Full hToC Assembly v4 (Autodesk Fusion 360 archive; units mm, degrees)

design "Full hToC Assembly" references "1 Slot Membrane", "hToc Bottom Component", "v10_component1"
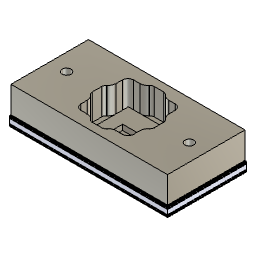
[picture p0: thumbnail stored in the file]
component_insert "Component Insert1"
component_insert "Component Insert2"
component_insert "Component Insert4"

design "v10_component1"
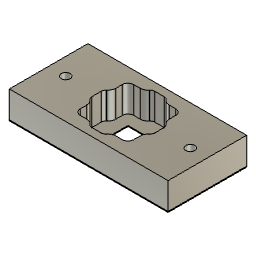
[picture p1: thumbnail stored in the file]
sketch "Sketch1" plane through (0, 0, 0) normal (0, 0, 1) x axis (1, 0, 0)
  line L1 (17.82, 5.59) -> (0, 5.59)
  line L2 (17.82, 8.82) -> (17.82, 0)
  line L3 (9.8201, 1.0463) -> (9.8489, 1.0851)
  line L4 (6.544, 1.41) -> (7.2771, 1.41)
  line L5 (10.5429, 7.41) -> (11.276, 7.41)
  line L6 (12.2349, 3.4711) -> (12.2737, 3.4999)
  line L7 (1.92, 4.41) -> (15.9, 4.41)
  line L8 (0, 3.621) -> (17.82, 3.621)
  line L9 (12.2737, 5.3201) -> (12.2349, 5.3489)
  line L10 (10.09, 0) -> (10.09, 8.82)
  line L11 (11.276, 1.41) -> (10.5429, 1.41)
  line L12 (9.699, 8.82) -> (9.699, 0)
  line L13 (5.5851, 5.3489) -> (5.5463, 5.3201)
  line L14 (12.437, 4.9474) -> (12.437, 3.8726)
  line L15 (17.82, 4.41) -> (15.9, 4.41)
  line L16 (15.9, 8.82) -> (15.9, 4.41)
  line L17 (5.5463, 3.4999) -> (5.5851, 3.4711)
  line L18 (17.82, 0) -> (0, 0)
  line L19 (17.82, 5.199) -> (0, 5.199)
  line L20 (17.82, 3.23) -> (0, 3.23)
  line L21 (0, 0) -> (0, 8.82)
  line L22 (11.91, 2.7771) -> (11.91, 2.044)
  line L23 (1.92, 4.41) -> (0, 4.41)
  line L24 (8.3726, 0.883) -> (9.4474, 0.883)
  line L25 (5.91, 2.7771) -> (5.91, 2.044)
  line L26 (1.92, 0) -> (1.92, 4.41)
  line L27 (15.9, 0) -> (15.9, 4.41)
  line L28 (9.4474, 7.937) -> (8.3726, 7.937)
  line L29 (5.383, 3.8726) -> (5.383, 4.9474)
  line L30 (9.8489, 7.7349) -> (9.8201, 7.7737)
  line L31 (5.91, 6.0429) -> (5.91, 6.776)
  line L32 (7.2771, 7.41) -> (6.544, 7.41)
  line L33 (7.9999, 7.7737) -> (7.9711, 7.7349)
  line L34 (8.121, 0) -> (8.121, 8.82)
  line L35 (1.92, 8.82) -> (1.92, 4.41)
  line L36 (7.9999, 1.0463) -> (7.9711, 1.0851)
  line L37 (11.91, 6.0429) -> (11.91, 6.776)
  line L38 (0, 8.82) -> (17.82, 8.82)
  line L39 (7.73, 8.82) -> (7.73, 0)
  arc A1 centre (12.81, 6.0429) radius 0.9 clockwise from (12.2737, 5.3201) to (11.91, 6.0429)
  arc A2 centre (11.937, 3.8726) radius 0.5 clockwise from (12.437, 3.8726) to (12.2349, 3.4711)
  arc A3 centre (9.4474, 1.383) radius 0.5 clockwise from (9.8489, 1.0851) to (9.4474, 0.883)
  arc A4 centre (11.276, 6.776) radius 0.634 clockwise from (11.276, 7.41) to (11.91, 6.776)
  arc A5 centre (9.4474, 7.437) radius 0.5 clockwise from (9.4474, 7.937) to (9.8489, 7.7349)
  arc A6 centre (11.937, 4.9474) radius 0.5 clockwise from (12.2349, 5.3489) to (12.437, 4.9474)
  arc A7 centre (10.5429, 8.31) radius 0.9 clockwise from (10.5429, 7.41) to (9.8201, 7.7737)
  circle C1 centre (15.9, 4.41) radius 0.5
  circle C2 centre (1.92, 4.41) radius 0.5
  arc A8 centre (8.3726, 7.437) radius 0.5 clockwise from (7.9711, 7.7349) to (8.3726, 7.937)
  arc A9 centre (10.5429, 0.51) radius 0.9 clockwise from (9.8201, 1.0463) to (10.5429, 1.41)
  arc A10 centre (5.01, 6.0429) radius 0.9 clockwise from (5.91, 6.0429) to (5.5463, 5.3201)
  arc A11 centre (5.883, 3.8726) radius 0.5 clockwise from (5.5851, 3.4711) to (5.383, 3.8726)
  arc A12 centre (8.3726, 1.383) radius 0.5 clockwise from (8.3726, 0.883) to (7.9711, 1.0851)
  arc A13 centre (6.544, 2.044) radius 0.634 clockwise from (6.544, 1.41) to (5.91, 2.044)
  arc A14 centre (5.883, 4.9474) radius 0.5 clockwise from (5.383, 4.9474) to (5.5851, 5.3489)
  arc A15 centre (7.2771, 8.31) radius 0.9 clockwise from (7.9999, 7.7737) to (7.2771, 7.41)
  arc A16 centre (5.01, 2.7771) radius 0.9 clockwise from (5.5463, 3.4999) to (5.91, 2.7771)
  arc A17 centre (12.81, 2.7771) radius 0.9 clockwise from (11.91, 2.7771) to (12.2737, 3.4999)
  arc A18 centre (11.276, 2.044) radius 0.634 clockwise from (11.91, 2.044) to (11.276, 1.41)
  arc A19 centre (7.2771, 0.51) radius 0.9 clockwise from (7.2771, 1.41) to (7.9999, 1.0463)
  arc A20 centre (6.544, 6.776) radius 0.634 clockwise from (5.91, 6.776) to (6.544, 7.41)
  point P28 (0, 0)
  point P80 (0, 0)
  point P29 (1.92, 4.41)
  point P34 (1.92, 4.41)
  point P35 (1.92, 8.82)
  point P31 (1.92, 4.41)
  point P30 (1.92, 0)
  point P15 (15.9, 4.41)
  point P39 (15.9, 4.41)
  point P38 (15.9, 8.82)
  point P36 (15.9, 4.41)
  point P37 (15.9, 0)
  point P5 (15.9, 4.41)
  point P6 (17.82, 4.41)
  point P27 (15.9, 4.41)
  point P82 (1.92, 4.41)
  point P33 (0, 4.41)
  point P32 (1.92, 4.41)
  point P98 (0, 5.199)
  point P95 (17.82, 5.199)
  point P89 (17.82, 3.621)
  point P90 (0, 3.621)
  point P41 (0, 3.23)
  point P97 (0, 5.59)
  point P93 (17.82, 5.59)
  point P96 (8.121, 8.82)
  point P92 (8.121, 0)
  point P81 (9.699, 0)
  point P83 (9.699, 8.82)
  point P88 (10.09, 8.82)
  point P84 (10.09, 0)
  point P91 (7.73, 0)
  point P94 (7.73, 8.82)
  point P65 (11.276, 1.41)
  point P20 (11.91, 6.776)
  point P57 (6.544, 7.41)
  point P22 (5.91, 2.044)
  horizontal L18
  vertical L2
  horizontal L38
  vertical L21
  coincident P28 P80
  coincident P29 P34
  coincident P35 L38
  perpendicular L35 L38
  coincident P29 P31
  coincident P30 L18
  perpendicular L18 L26
  coincident P15 P39
  coincident P38 L38
  perpendicular L16 L38
  coincident P15 P36
  coincident P37 L18
  perpendicular L18 L27
  coincident P5 P15
  midpoint P6 L2
  coincident P15 P27
  coincident P29 P82
  perpendicular L7 L26
  midpoint P33 L21
  coincident P29 P32
  perpendicular L23 L26
  coincident P98 L21
  coincident P95 L2
  perpendicular L2 L19
  coincident P89 L2
  coincident P90 L21
  perpendicular L8 L21
  coincident P41 L21
  perpendicular L20 L21
  perpendicular L4 L21
  coincident P97 L21
  coincident P93 L2
  perpendicular L1 L2
  perpendicular L5 L21
  coincident P96 L38
  coincident P92 L18
  perpendicular L18 L34
  coincident P81 L18
  coincident P83 L38
  perpendicular L12 L38
  coincident P88 L38
  coincident P84 L18
  perpendicular L10 L18
  perpendicular L22 L38
  coincident P91 L18
  coincident P94 L38
  perpendicular L38 L39
  perpendicular L18 L31
  perpendicular L18 L29
  perpendicular L14 L38
  perpendicular L2 L28
  perpendicular L21 L24
  tangent L31 A20
  tangent L5 A20
  tangent L5 A4
  tangent A4 L22
  tangent L4 A13
  tangent A13 L31
  tangent L4 A18
  tangent L22 A18
  coincident P65 L4
  tangent L4 A19
  tangent A19 L36
  tangent A12 L36
  tangent L24 A12
  tangent A3 L24
  tangent L3 A3
  tangent L3 A9
  tangent L11 A9
  coincident P20 L22
  tangent L22 A17
  tangent L6 A17
  tangent L6 A2
  tangent A2 L14
  tangent A6 L14
  tangent L9 A6
  tangent A1 L9
  tangent A1 L37
  coincident P57 L5
  tangent A7 L30
  tangent L5 A7
  tangent A5 L28
  tangent A5 L30
  tangent A15 L32
  tangent A15 L33
  tangent A8 L33
  tangent A8 L28
  coincident P22 L31
  tangent L13 A10
  tangent A10 L31
  tangent A14 L29
  tangent L13 A14
  tangent L17 A11
  tangent A11 L29
  tangent L17 A16
  tangent L25 A16
  dimension "d1" distance L2 L21 = 17.82
  dimension "d2" distance L18 L38 = 8.82
  dimension "d3" diameter C2 = 1
  dimension "d4" diameter C1 = 1
  dimension "d5" distance L21 L26 = 1.92
  dimension "d6" distance L2 L27 = 1.92
  dimension "d7" distance L12 L34 = 1.578
  dimension "d8" distance L2 L12 = 8.121
  dimension "d9" distance L10 L39 = 2.36
  dimension "d10" distance L2 L10 = 7.73
  dimension "d11" distance L22 L31 = 6
  dimension "d12" distance L2 L22 = 5.91
  dimension "d13" distance L14 L29 = 7.054
  dimension "d14" distance L2 L14 = 5.383
  dimension "d15" distance L8 L19 = 1.578
  dimension "d16" distance L19 L38 = 3.621
  dimension "d17" distance L1 L20 = 2.36
  dimension "d18" distance L1 L38 = 3.23
  dimension "d19" distance L4 L5 = 6
  dimension "d20" distance L5 L38 = 1.41
  dimension "d21" distance L24 L28 = 7.054
  dimension "d22" distance L28 L38 = 0.883
  dimension "d23" radius A20 = 0.634
  dimension "d24" radius A4 = 0.634
  dimension "d25" radius A13 = 0.634
  dimension "d26" radius A18 = 0.634
  dimension "d27" radius A19 = 0.9
  dimension "d28" radius A12 = 0.5
  dimension "d29" radius A3 = 0.5
  dimension "d30" radius A9 = 0.9
  dimension "d31" radius A17 = 0.9
  dimension "d32" radius A2 = 0.5
  dimension "d33" radius A6 = 0.5
  dimension "d34" radius A1 = 0.9
  dimension "d35" radius A7 = 0.9
  dimension "d36" radius A5 = 0.5
  dimension "d37" radius A15 = 0.9
  dimension "d38" radius A8 = 0.5
  dimension "d39" radius A10 = 0.9
  dimension "d40" radius A14 = 0.5
  dimension "d41" radius A11 = 0.5
  dimension "d42" radius A16 = 0.9
extrude "Extrude1" new body sketch "Sketch1" along normal blind 3 bodies "L1 - ACRYLIC"
sketch "Sketch2" plane through (0, 0, 3) normal (0, 0, 1) x axis (-1, 0, 0)
  line L1 (-7.2771, -7.41) -> (-6.544, -7.41)
  line L2 (-7.9711, -7.7349) -> (-7.9999, -7.7737)
  line L3 (-9.4474, -7.937) -> (-8.3726, -7.937)
  line L4 (-9.8201, -7.7737) -> (-9.8489, -7.7349)
  line L5 (-11.276, -7.41) -> (-10.5429, -7.41)
  line L6 (-11.91, -6.0429) -> (-11.91, -6.776)
  line L7 (-12.2349, -5.3489) -> (-12.2737, -5.3201)
  line L8 (-12.437, -3.8726) -> (-12.437, -4.9474)
  line L9 (-12.2737, -3.4999) -> (-12.2349, -3.4711)
  line L10 (-11.91, -2.044) -> (-11.91, -2.7771)
  line L11 (-10.5429, -1.41) -> (-11.276, -1.41)
  line L12 (-9.8489, -1.0851) -> (-9.8201, -1.0463)
  line L13 (-8.3726, -0.883) -> (-9.4474, -0.883)
  line L14 (-7.9999, -1.0463) -> (-7.9711, -1.0851)
  line L15 (-6.544, -1.41) -> (-7.2771, -1.41)
  line L16 (-5.91, -2.7771) -> (-5.91, -2.044)
  line L17 (-5.5851, -3.4711) -> (-5.5463, -3.4999)
  line L18 (-5.383, -4.9474) -> (-5.383, -3.8726)
  line L19 (-5.5463, -5.3201) -> (-5.5851, -5.3489)
  line L20 (-5.91, -6.776) -> (-5.91, -6.0429)
  line L21 (0, -8.82) -> (-17.82, -8.82)
  line L22 (0, 0) -> (0, -8.82)
  line L23 (-17.82, 0) -> (0, 0)
  line L24 (-17.82, -8.82) -> (-17.82, 0)
  circle C1 centre (-1.92, -4.41) radius 0.5
  arc A1 centre (-7.2771, -8.31) radius 0.9 clockwise from (-7.9999, -7.7737) to (-7.2771, -7.41)
  arc A2 centre (-8.3726, -7.437) radius 0.5 clockwise from (-7.9711, -7.7349) to (-8.3726, -7.937)
  arc A3 centre (-9.4474, -7.437) radius 0.5 clockwise from (-9.4474, -7.937) to (-9.8489, -7.7349)
  arc A4 centre (-10.5429, -8.31) radius 0.9 clockwise from (-10.5429, -7.41) to (-9.8201, -7.7737)
  arc A5 centre (-11.276, -6.776) radius 0.634 clockwise from (-11.276, -7.41) to (-11.91, -6.776)
  arc A6 centre (-12.81, -6.0429) radius 0.9 clockwise from (-12.2737, -5.3201) to (-11.91, -6.0429)
  arc A7 centre (-11.937, -4.9474) radius 0.5 clockwise from (-12.2349, -5.3489) to (-12.437, -4.9474)
  arc A8 centre (-11.937, -3.8726) radius 0.5 clockwise from (-12.437, -3.8726) to (-12.2349, -3.4711)
  arc A9 centre (-12.81, -2.7771) radius 0.9 clockwise from (-11.91, -2.7771) to (-12.2737, -3.4999)
  arc A10 centre (-11.276, -2.044) radius 0.634 clockwise from (-11.91, -2.044) to (-11.276, -1.41)
  arc A11 centre (-10.5429, -0.51) radius 0.9 clockwise from (-9.8201, -1.0463) to (-10.5429, -1.41)
  arc A12 centre (-9.4474, -1.383) radius 0.5 clockwise from (-9.8489, -1.0851) to (-9.4474, -0.883)
  arc A13 centre (-8.3726, -1.383) radius 0.5 clockwise from (-8.3726, -0.883) to (-7.9711, -1.0851)
  arc A14 centre (-7.2771, -0.51) radius 0.9 clockwise from (-7.2771, -1.41) to (-7.9999, -1.0463)
  arc A15 centre (-6.544, -2.044) radius 0.634 clockwise from (-6.544, -1.41) to (-5.91, -2.044)
  arc A16 centre (-5.01, -2.7771) radius 0.9 clockwise from (-5.5463, -3.4999) to (-5.91, -2.7771)
  arc A17 centre (-5.883, -3.8726) radius 0.5 clockwise from (-5.5851, -3.4711) to (-5.383, -3.8726)
  arc A18 centre (-5.883, -4.9474) radius 0.5 clockwise from (-5.383, -4.9474) to (-5.5851, -5.3489)
  arc A19 centre (-5.01, -6.0429) radius 0.9 clockwise from (-5.91, -6.0429) to (-5.5463, -5.3201)
  arc A20 centre (-6.544, -6.776) radius 0.634 clockwise from (-5.91, -6.776) to (-6.544, -7.41)
  circle C2 centre (-15.9, -4.41) radius 0.5
sketch "Sketch3" plane through (0, 0, 0) normal (0, 0, -1) x axis (1, 0, 0)
  line L1 (6.544, -7.41) -> (7.2771, -7.41)
  line L2 (5.91, -6.0429) -> (5.91, -6.776)
  line L3 (5.5851, -5.3489) -> (5.5463, -5.3201)
  line L4 (5.383, -3.8726) -> (5.383, -4.9474)
  line L5 (5.5463, -3.4999) -> (5.5851, -3.4711)
  line L6 (5.91, -2.044) -> (5.91, -2.7771)
  line L7 (7.2771, -1.41) -> (6.544, -1.41)
  line L8 (7.9711, -1.0851) -> (7.9999, -1.0463)
  line L9 (9.4474, -0.883) -> (8.3726, -0.883)
  line L10 (9.8201, -1.0463) -> (9.8489, -1.0851)
  line L11 (11.276, -1.41) -> (10.5429, -1.41)
  line L12 (11.91, -2.7771) -> (11.91, -2.044)
  line L13 (12.2349, -3.4711) -> (12.2737, -3.4999)
  line L14 (12.437, -4.9474) -> (12.437, -3.8726)
  line L15 (12.2737, -5.3201) -> (12.2349, -5.3489)
  line L16 (11.91, -6.776) -> (11.91, -6.0429)
  line L17 (10.5429, -7.41) -> (11.276, -7.41)
  line L18 (9.8489, -7.7349) -> (9.8201, -7.7737)
  line L19 (8.3726, -7.937) -> (9.4474, -7.937)
  line L20 (7.9999, -7.7737) -> (7.9711, -7.7349)
  line L21 (17.82, -8.82) -> (0, -8.82)
  line L22 (17.82, 0) -> (17.82, -8.82)
  line L23 (0, 0) -> (17.82, 0)
  line L24 (0, -8.82) -> (0, 0)
  line L25 (17.82, -8.82) -> (17.82, 0)
  line L26 (17.82, 0) -> (0, 0)
  line L27 (7.21, -2.71) -> (10.61, -2.71)
  line L28 (10.61, -2.71) -> (10.61, -6.11)
  line L29 (10.61, -6.11) -> (7.21, -6.11)
  line L30 (0, 0) -> (0, -8.82)
  line L31 (7.21, -6.11) -> (7.21, -2.71)
  line L32 (15.9, -4.41) -> (1.92, -4.41)
  line L33 (0, -4.41) -> (1.92, -4.41)
  line L34 (17.82, -4.41) -> (15.9, -4.41)
  line L35 (0, -8.82) -> (17.82, -8.82)
  circle C1 centre (1.92, -4.41) radius 0.5
  arc A1 centre (6.544, -6.776) radius 0.634 clockwise from (6.544, -7.41) to (5.91, -6.776)
  arc A2 centre (5.01, -6.0429) radius 0.9 clockwise from (5.5463, -5.3201) to (5.91, -6.0429)
  arc A3 centre (5.883, -4.9474) radius 0.5 clockwise from (5.5851, -5.3489) to (5.383, -4.9474)
  arc A4 centre (5.883, -3.8726) radius 0.5 clockwise from (5.383, -3.8726) to (5.5851, -3.4711)
  arc A5 centre (5.01, -2.7771) radius 0.9 clockwise from (5.91, -2.7771) to (5.5463, -3.4999)
  arc A6 centre (6.544, -2.044) radius 0.634 clockwise from (5.91, -2.044) to (6.544, -1.41)
  arc A7 centre (7.2771, -0.51) radius 0.9 clockwise from (7.9999, -1.0463) to (7.2771, -1.41)
  arc A8 centre (8.3726, -1.383) radius 0.5 clockwise from (7.9711, -1.0851) to (8.3726, -0.883)
  arc A9 centre (9.4474, -1.383) radius 0.5 clockwise from (9.4474, -0.883) to (9.8489, -1.0851)
  arc A10 centre (10.5429, -0.51) radius 0.9 clockwise from (10.5429, -1.41) to (9.8201, -1.0463)
  arc A11 centre (11.276, -2.044) radius 0.634 clockwise from (11.276, -1.41) to (11.91, -2.044)
  arc A12 centre (12.81, -2.7771) radius 0.9 clockwise from (12.2737, -3.4999) to (11.91, -2.7771)
  arc A13 centre (11.937, -3.8726) radius 0.5 clockwise from (12.2349, -3.4711) to (12.437, -3.8726)
  arc A14 centre (11.937, -4.9474) radius 0.5 clockwise from (12.437, -4.9474) to (12.2349, -5.3489)
  arc A15 centre (12.81, -6.0429) radius 0.9 clockwise from (11.91, -6.0429) to (12.2737, -5.3201)
  arc A16 centre (11.276, -6.776) radius 0.634 clockwise from (11.91, -6.776) to (11.276, -7.41)
  arc A17 centre (10.5429, -8.31) radius 0.9 clockwise from (9.8201, -7.7737) to (10.5429, -7.41)
  arc A18 centre (9.4474, -7.437) radius 0.5 clockwise from (9.8489, -7.7349) to (9.4474, -7.937)
  arc A19 centre (8.3726, -7.437) radius 0.5 clockwise from (8.3726, -7.937) to (7.9711, -7.7349)
  arc A20 centre (7.2771, -8.31) radius 0.9 clockwise from (7.2771, -7.41) to (7.9999, -7.7737)
  circle C2 centre (15.9, -4.41) radius 0.5
  circle C3 centre (1.92, -4.41) radius 0.625
  circle C4 centre (15.9, -4.41) radius 0.625
  point P69 (0, 0)
  point P70 (0, 0)
  point P72 (1.92, -4.41)
  point P75 (1.92, -4.41)
  point P68 (15.9, -4.41)
  point P73 (15.9, -4.41)
  point P79 (17.82, -4.41)
  point P76 (1.92, -4.41)
  point P74 (0, -4.41)
  point P71 (7.21, -6.11)
  point P78 (7.21, -2.71)
  coincident P69 P70
  coincident P72 P75
  coincident P68 P73
  parallel L32 L35
  coincident P79 L25
  perpendicular L25 L34
  coincident P72 P76
  coincident P74 L30
  perpendicular L30 L33
  dimension "d45" distance L25 L30 = 17.82
  dimension "d46" distance L26 L35 = 8.82
  dimension "d47" diameter C3 = 1.25
  dimension "d48" diameter C4 = 1.25
  dimension "d49" distance P72 L30 = 1.92
  dimension "d50" distance P68 L25 = 1.92
  dimension "d51" distance L32 L35 = 4.41
  dimension "d52" distance P71 P78 = 3.4
  dimension "d53" distance L28 L31 = 3.4
  dimension "d54" distance L29 L35 = 2.71
  dimension "d55" distance L25 L28 = 7.21
place_component sketch "Sketch3"
extrude "Extrude1" new body sketch "Sketch3" profile of L1 A1 L2 A2 L3 A3 L4 A4 L5 A5 L6 A6 L7 A7 L8 A8 L9 A9 L10 A10 L11 A11 L12 A12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 along normal blind 0.0508
extrude "Extrude1" new body of existing geometry blind 0.0508
component_from_bodies "Body->Comp2"
place_component sketch "Sketch3"
extrude "Extrude1" new body sketch "Sketch3" along normal blind 0.0508 bodies "Layer 2"
component_from_bodies "Body->Comp1"
sketch "Sketch4" plane through (0, 0, -0.0508) normal (0, 0, -1) x axis (1, 0, 0)
  line L1 (7.21, -2.71) -> (7.21, -6.11)
  line L2 (10.61, -2.71) -> (7.21, -2.71)
  line L3 (10.61, -6.11) -> (10.61, -2.71)
  line L4 (7.21, -6.11) -> (10.61, -6.11)
  line L5 (17.82, 0) -> (17.82, -8.82)
  line L6 (0, 0) -> (17.82, 0)
  line L7 (0, -8.82) -> (0, 0)
  line L8 (17.82, -8.82) -> (0, -8.82)
  line L9 (5.5463, -3.4999) -> (5.5851, -3.4711)
  line L10 (9.8201, -1.0463) -> (9.8489, -1.0851)
  line L11 (9.4474, -0.883) -> (8.3726, -0.883)
  line L12 (11.276, -1.41) -> (10.5429, -1.41)
  line L13 (11.91, -2.7771) -> (11.91, -2.044)
  line L14 (5.91, -2.044) -> (5.91, -2.7771)
  line L15 (12.2349, -3.4711) -> (12.2737, -3.4999)
  line L16 (17.82, -8.82) -> (17.82, 0)
  line L17 (7.21, -2.71) -> (10.61, -2.71)
  line L18 (0, 0) -> (0, -8.82)
  line L19 (10.61, -2.71) -> (10.61, -6.11)
  line L20 (15.9, -4.41) -> (1.92, -4.41)
  line L21 (17.82, 0) -> (0, 0)
  line L22 (10.61, -6.11) -> (7.21, -6.11)
  line L23 (17.82, -8.82) -> (0, -8.82)
  line L24 (0, -8.82) -> (17.82, -8.82)
  line L25 (17.82, -4.41) -> (15.9, -4.41)
  line L26 (8.3726, -7.937) -> (9.4474, -7.937)
  line L27 (0, 0) -> (17.82, 0)
  line L28 (9.8489, -7.7349) -> (9.8201, -7.7737)
  line L29 (10.5429, -7.41) -> (11.276, -7.41)
  line L30 (11.91, -6.776) -> (11.91, -6.0429)
  line L31 (12.2737, -5.3201) -> (12.2349, -5.3489)
  line L32 (12.437, -4.9474) -> (12.437, -3.8726)
  line L33 (0, -8.82) -> (0, 0)
  line L34 (7.9999, -7.7737) -> (7.9711, -7.7349)
  line L35 (5.383, -3.8726) -> (5.383, -4.9474)
  line L36 (5.5851, -5.3489) -> (5.5463, -5.3201)
  line L37 (5.91, -6.0429) -> (5.91, -6.776)
  line L38 (6.544, -7.41) -> (7.2771, -7.41)
  line L39 (17.82, 0) -> (17.82, -8.82)
  line L40 (7.9711, -1.0851) -> (7.9999, -1.0463)
  line L41 (7.2771, -1.41) -> (6.544, -1.41)
  line L42 (0, -4.41) -> (1.92, -4.41)
  line L43 (7.21, -6.11) -> (7.21, -2.71)
  circle C1 centre (15.9, -4.41) radius 0.5
  circle C2 centre (1.92, -4.41) radius 0.5
  arc A1 centre (11.937, -4.9474) radius 0.5 clockwise from (12.437, -4.9474) to (12.2349, -5.3489)
  circle C3 centre (1.92, -4.41) radius 0.625
  arc A2 centre (12.81, -6.0429) radius 0.9 clockwise from (11.91, -6.0429) to (12.2737, -5.3201)
  arc A3 centre (11.276, -6.776) radius 0.634 clockwise from (11.91, -6.776) to (11.276, -7.41)
  arc A4 centre (9.4474, -7.437) radius 0.5 clockwise from (9.8489, -7.7349) to (9.4474, -7.937)
  arc A5 centre (10.5429, -8.31) radius 0.9 clockwise from (9.8201, -7.7737) to (10.5429, -7.41)
  circle C4 centre (15.9, -4.41) radius 0.625
  arc A6 centre (6.544, -6.776) radius 0.634 clockwise from (6.544, -7.41) to (5.91, -6.776)
  circle C5 centre (1.92, -4.41) radius 0.5
  arc A7 centre (5.01, -6.0429) radius 0.9 clockwise from (5.5463, -5.3201) to (5.91, -6.0429)
  arc A8 centre (5.883, -4.9474) radius 0.5 clockwise from (5.5851, -5.3489) to (5.383, -4.9474)
  arc A9 centre (8.3726, -7.437) radius 0.5 clockwise from (8.3726, -7.937) to (7.9711, -7.7349)
  arc A10 centre (7.2771, -8.31) radius 0.9 clockwise from (7.2771, -7.41) to (7.9999, -7.7737)
  circle C6 centre (15.9, -4.41) radius 0.5
  arc A11 centre (5.883, -3.8726) radius 0.5 clockwise from (5.383, -3.8726) to (5.5851, -3.4711)
  arc A12 centre (5.01, -2.7771) radius 0.9 clockwise from (5.91, -2.7771) to (5.5463, -3.4999)
  arc A13 centre (6.544, -2.044) radius 0.634 clockwise from (5.91, -2.044) to (6.544, -1.41)
  arc A14 centre (7.2771, -0.51) radius 0.9 clockwise from (7.9999, -1.0463) to (7.2771, -1.41)
  arc A15 centre (8.3726, -1.383) radius 0.5 clockwise from (7.9711, -1.0851) to (8.3726, -0.883)
  arc A16 centre (9.4474, -1.383) radius 0.5 clockwise from (9.4474, -0.883) to (9.8489, -1.0851)
  arc A17 centre (10.5429, -0.51) radius 0.9 clockwise from (10.5429, -1.41) to (9.8201, -1.0463)
  arc A18 centre (11.276, -2.044) radius 0.634 clockwise from (11.276, -1.41) to (11.91, -2.044)
  arc A19 centre (12.81, -2.7771) radius 0.9 clockwise from (12.2737, -3.4999) to (11.91, -2.7771)
  arc A20 centre (11.937, -3.8726) radius 0.5 clockwise from (12.2349, -3.4711) to (12.437, -3.8726)
  point P67 (0, 0)
  point P68 (0, 0)
  point P62 (1.92, -4.41)
  point P64 (1.92, -4.41)
  point P54 (15.9, -4.41)
  point P66 (15.9, -4.41)
  point P57 (17.82, -4.41)
  point P65 (1.92, -4.41)
  point P39 (0, -4.41)
  point P61 (7.21, -2.71)
  point P70 (7.21, -6.11)
  coincident P67 P68
  coincident P62 P64
  coincident P54 P66
  parallel L20 L24
  coincident P57 L16
  perpendicular L16 L25
  coincident P62 P65
  coincident P39 L18
  perpendicular L18 L42
  dimension "d71" distance L16 L18 = 17.82
  dimension "d72" distance L21 L24 = 8.82
  dimension "d73" diameter C3 = 1.25
  dimension "d74" diameter C4 = 1.25
  dimension "d75" distance P62 L18 = 1.92
  dimension "d76" distance P66 L16 = 1.92
  dimension "d77" distance L20 L24 = 4.41
  dimension "d78" distance P61 P70 = 3.4
  dimension "d79" distance L19 L43 = 3.4
  dimension "d80" distance L22 L24 = 2.71
  dimension "d81" distance L16 L19 = 7.21
place_component sketch "Sketch4"
extrude "Extrude1" new body sketch "Sketch4" profile of L1 L2 L3 L4 L5 L6 L7 L8 A1 L9 L10 L11 L12 L13 L14 L15 L16 C3 L17 A2 A3 A4 A5 L18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 along normal blind 0.0508
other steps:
base_feature "Base Feature1" bodies "L1 - ACRYLIC"
create_component "CreateComponent1" sketch "Sketch3"
create_component "CreateComponent3"
base_feature "Base Feature1" bodies "L1 - ACRYLIC"
remove_body "RemoveBody1"
create_component "CreateComponent4" sketch "Sketch4"
create_component "CreateComponent5" sketch "Sketch3"
create_component "CreateComponent6"
create_component "CreateComponent7"
remove_body "RemoveBody2"
named bodies: "L1 - ACRYLIC", "Layer 2"

design "hToc Bottom Component"
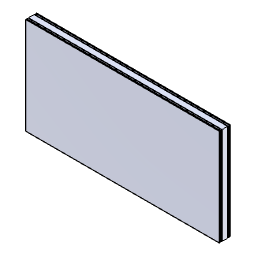
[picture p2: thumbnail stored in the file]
description: HOOPS Exchange Step
part number: root
description: Part Number
part number: hToc Bottom L10-1
part number: hToc Bottom L8-1
part number: hToc Bottom L9-1
part number: hToc Bottom L7-1
part number: hToc Bottom L6-1
part number: hToc Bottom L5-1
part number: hToc Bottom L4-1
part number: hToc Bottom L3-1
part number: hToc Bottom L2-1
base_feature "Base Feature1"
base_feature "Base Feature1"
base_feature "Base Feature1"
base_feature "Base Feature1"
base_feature "Base Feature1"
base_feature "Base Feature1"
base_feature "Base Feature1"
base_feature "Base Feature1"
base_feature "Base Feature1"
base_feature "Base Feature1"
base_feature "Base Feature1"
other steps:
create_component "CreateComponent1"
create_component "CreateComponent1"
create_component "CreateComponent2"
create_component "CreateComponent3"
create_component "CreateComponent4"
create_component "CreateComponent5"
create_component "CreateComponent6"
create_component "CreateComponent7"
create_component "CreateComponent8"
create_component "CreateComponent9"
create_component "CreateComponent10"
create_component "CreateComponent11"

design "1 Slot Membrane"
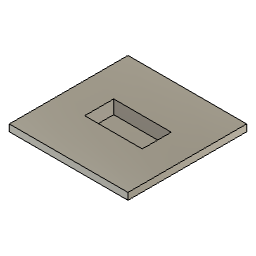
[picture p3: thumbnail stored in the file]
sketch "Sketch1" plane through (0, 0, 0) normal (0, 0, 1) x axis (1, 0, 0)
  line L1 (5.4, 0) -> (0, 0)
  line L2 (5.4, 5.4) -> (5.4, 0)
  line L3 (0, 5.4) -> (5.4, 5.4)
  line L4 (0, 0) -> (0, 5.4)
  point P1 (0, 0)
  point P2 (0, 0)
  horizontal L1
  vertical L2
  horizontal L3
  vertical L4
  coincident P1 P2
  dimension "d1" distance L2 L4 = 5.4
  dimension "d2" distance L1 L3 = 5.4
extrude "Extrude1" new body sketch "Sketch1" along normal blind 0.31
sketch "Sketch2" plane through (0, 0, 0.31) normal (0, 0, 1) x axis (-1, 0, 0)
  line L1 (-1.7, -2.35) -> (-3.7, -2.35)
  line L2 (-1.7, -3.05) -> (-1.7, -2.35)
  line L3 (-3.7, -3.05) -> (-1.7, -3.05)
  line L4 (-3.7, -2.35) -> (-3.7, -3.05)
  line L5 (0, 0) -> (0, -5.4)
  line L6 (-5.4, 0) -> (0, 0)
  line L7 (-5.4, -5.4) -> (-5.4, 0)
  line L8 (0, -5.4) -> (-5.4, -5.4)
  point P1 (0, 0)
  horizontal L1
  vertical L2
  horizontal L3
  vertical L4
  dimension "d8" distance L1 L3 = 0.7
  dimension "d9" distance L2 L4 = 2
  dimension "d10" distance P1 L2 = 1.7
  dimension "d11" distance P1 L1 = 2.35
extrude "Extrude2" cut sketch "Sketch2" profile of L1 L2 L3 L4 against normal blind 3
chamfer "Chamfer2" distance 0.31 Rotate Angle 45
component_from_bodies "Body->Comp"
sketch "Sketch3" plane through (0, 0, 0) normal (0, 0, -1) x axis (1, 0, 0)
  line L1 (1.7, -2.35) -> (1.7, -3.05)
  line L2 (3.7, -2.35) -> (1.7, -2.35)
  line L3 (3.7, -3.05) -> (3.7, -2.35)
  line L4 (1.7, -3.05) -> (3.7, -3.05)
  line L5 (0, -5.4) -> (0, 0)
  line L6 (5.4, -5.4) -> (0, -5.4)
  line L7 (5.4, 0) -> (5.4, -5.4)
  line L8 (0, 0) -> (5.4, 0)
  line L9 (0, -5.4) -> (5.4, -5.4)
  line L10 (0, 0) -> (0, -5.4)
  line L11 (5.4, 0) -> (0, 0)
  line L12 (5.4, -5.4) -> (5.4, 0)
  point P6 (0, 0)
  point P12 (0, 0)
  point P8 (5.4, -5.4)
  point P10 (5.4, -5.4)
  horizontal L9
  vertical L10
  horizontal L11
  vertical L12
  coincident P6 P12
  coincident P8 P10
place_component sketch "Sketch3"
extrude "Extrude1" new body sketch "Sketch3" along normal blind 0.0001 (= "100 nm")
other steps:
base_feature "Base Feature"
create_component "CreateComponent1"
remove_body "RemoveBody1"
create_component "CreateComponent2" sketch "Sketch3"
